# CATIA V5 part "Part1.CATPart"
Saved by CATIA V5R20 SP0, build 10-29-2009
Part number: 花瓶
Material "Water": density 1000 kg/m3
Material "Cloudy Sky"
Bounding box of the stored display mesh (mm): x -39.948 to 39.948, y -39.954 to 39.914, z 0 to 113.198
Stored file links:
  G:\新建文件夹\Part1.CATPart
  C:\Program Files\Dassault Systemes\B20\win_b64\startup\materials\Catalog.CATMaterial
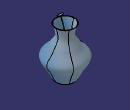
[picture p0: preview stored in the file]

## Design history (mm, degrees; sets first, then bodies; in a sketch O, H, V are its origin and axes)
Body1 (main body), material "Cloudy Sky"
  Plane1: type Offset, RefPlane xy-plane, Offset 20
  Plane2: type Offset, RefPlane Plane1, Offset 20
  Plane3: type Offset, RefPlane Plane2, Offset 20
  Plane4: type Offset, RefPlane Plane3, Offset 20
  Plane5: type Offset, RefPlane Plane4, Offset 20
  Sketch1 on Plane5, origin (0, 0, 100), H (1, 0, 0), V (0, 1, 0)
    circle A1 centre (0, 0) radius 20
  Sketch2 on Plane4, origin (0, 0, 80), H (1, 0, 0), V (0, 1, 0)
    circle A1 centre (0, 0) radius 15
    radius A1 = 15
  Sketch3 on Plane3, origin (0, 0, 60), H (1, 0, 0), V (0, 1, 0)
    circle A1 centre (0, 0) radius 25
    radius A1 = 25
  Sketch4 on Plane2, origin (0, 0, 40), H (1, 0, 0), V (0, 1, 0)
    circle A1 centre (0, 0) radius 40
  Sketch5 on Plane1, origin (0, 0, 20), H (1, 0, 0), V (0, 1, 0)
    circle A1 centre (0, 0) radius 30
  Sketch6 on xy-plane, origin (0, 0, 0), H (1, 0, 0), V (0, 1, 0)
    circle A1 centre (0, 0) radius 20
  Loft1: solid, Sections (Sketch1; Sketch2; Sketch3; Sketch4; Sketch5; Sketch6)
  Shell1: IntOffset 1, Face face of Loft1, ExtOffset 0
Body2, material "Water"
  Sketch7 on yz-plane, origin (0, 0, 0), H (0, 1, 0), V (0, 0, 1)
    axis line L1 (0, 108.5052) -> (0, -10.8485)
    point P1 (0, 108.5052)
    line L2 (0, 29.7425) -> (26.6663, 29.7425)
    point P3 (0, 29.7425)
    point P4 (26.6663, 29.7425)
    spline S1 through (26.6663, 29.7425) (23.4338, 10.6567) (18.3155, 0)
    line L3 (18.3155, 0) -> (0, 0)
    point P5 (18.3155, 0)
    point P6 (26.6663, 29.7425)
    point P7 (18.3155, 0)
    coincidence: P1 V, P3 L1, P6 P4, P7 H, P7 P5
    vertical: L1 V
    horizontal: L2 H, L3 H
  Shaft1: profile Sketch7, axis Sketch7.L1, angle 360
Body3
  Sketch8 on yz-plane, origin (0, 0, 0), H (0, 1, 0), V (0, 0, 1)
    spline S1 through (-10, 110) (0, 80) (-10, 10)
  Plane6: type Normal, Curve Sketch8, RefPoint vertex of Sketch8
  Sketch9 on Plane6, origin (0, -45.3382, 92.7204), H (1, 0, 0), V (0, 0.8984, 0.4393)
    circle A1 centre (0, 39.0159) radius 0.5
    point P1 (0, 39.0159)
    radius A1 = 0.5
    coincidence: P1 V
  Rib1: profile Sketch9, centre curve Sketch8, thin wall 1
  Sketch10 on Plane6, origin (0, -45.3382, 92.7204), H (1, 0, 0), V (0, 0.8984, 0.4393)
    point P1 (0, 39.3875)
    point P2 (5.177, 37.9856)
    point P3 (3.8026, 43.17)
    point P4 (-1.3744, 44.5719)
    point P5 (-5.177, 40.7895)
    point P6 (-3.8026, 35.6051)
    point P7 (1.3744, 34.2032)
    point P8 (4.4898, 40.5778)
    line L1 (5.177, 37.9856) -> (3.8026, 43.17)
    line L2 (3.8026, 43.17) -> (-1.3744, 44.5719)
    line L3 (-1.3744, 44.5719) -> (-5.177, 40.7895)
    line L4 (-5.177, 40.7895) -> (-3.8026, 35.6051)
    line L5 (-3.8026, 35.6051) -> (1.3744, 34.2032)
    line L6 (1.3744, 34.2032) -> (5.177, 37.9856)
    construction line L7 (0, 39.3875) -> (4.4898, 40.5778)
    construction circle A1 centre (0, 39.3875) radius 5.3635
    construction arc A2 centre (-3.8026, 35.6051) radius 5.3635 from (-5.177, 40.7895) to (1.3744, 34.2032) cw
    construction arc A3 centre (3.8026, 43.17) radius 5.3635 from (-1.3744, 44.5719) to (5.177, 37.9856) ccw
    coincidence: P1 V, A1 P2, A1 P3, A1 P4, A1 P5, A1 P6, A1 P7, A2 P1, A3 P1
    midpoint: P8 L1
    parallelism: L1 L4
  Pad1: profile Sketch10, direction (0, -0.4393, 0.8984), length 1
